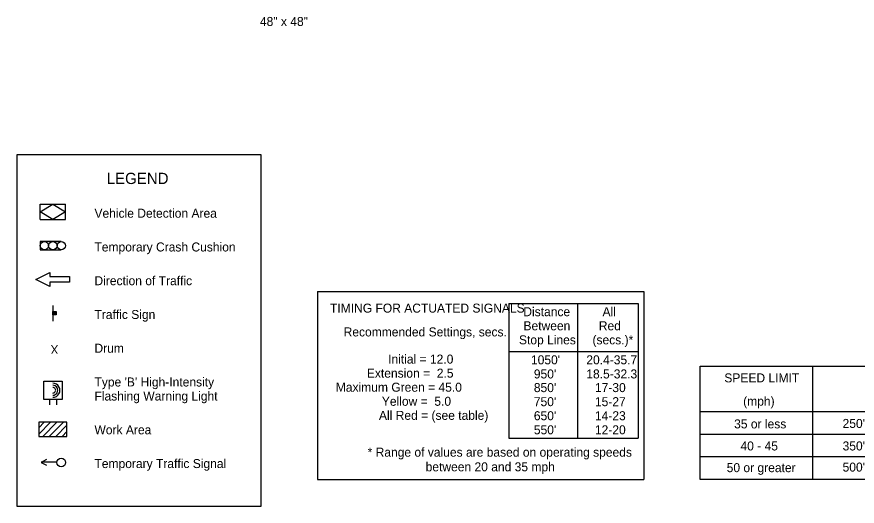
# Model space of a CAD drawing. Extents: x 10124 to 16850, y 7924 to 12166.
# Drawn here: x 13749 to 15243, y 7951 to 8821 of the extents above; entities that cross this region are included whole.
import ezdxf

# ---------------------------------------------------------------- set-up
doc = ezdxf.new("R2010")
doc.units = 0
for name, color, linetype in [('Level 2', 7, 'Continuous'), ('Level 3', 7, 'Continuous'), ('Level 4', 7, 'Continuous')]:
    doc.layers.add(name, color=color, linetype=linetype)

msp = doc.modelspace()

# ---------------------------------------------------------------- linework, layer by layer
at = {"layer": 'Level 2'}
for p, q in [((13790.9, 8460.9), (13790.9, 8487.9)), ((13790.9, 8487.9), (13835.9, 8487.9)), ((13835.9, 8460.9), (13835.9, 8487.9)), ((13790.9, 8460.9), (13835.9, 8460.9)), ((13790.9, 8421.9), (13790.9, 8406.9)), ((13828.4, 8421.9), (13790.9, 8421.9)), ((13790.9, 8406.9), (13828.4, 8406.9)), ((14283.7, 8333), (14283.7, 7999)), ((14283.7, 8333), (14863.7, 8333)), ((14863.7, 8333), (14863.7, 7999)), ((13813.4, 8308), (13813.4, 8280.5)), ((13813.8, 8291.6), (13813.8, 8297.2)), ((13814.1, 8297.2), (13814.1, 8291.6)), ((13814.4, 8291.6), (13814.4, 8297.2)), ((13814.6, 8297.2), (13814.6, 8291.6)), ((13814.9, 8291.6), (13814.9, 8297.2)), ((13815.1, 8297.2), (13815.1, 8291.6)), ((13815.4, 8291.6), (13815.4, 8297.2)), ((13815.7, 8297.2), (13815.7, 8291.6)), ((13815.9, 8291.6), (13815.9, 8297.2)), ((13816.2, 8297.2), (13816.2, 8291.6)), ((13816.6, 8291.6), (13816.6, 8297.2)), ((13817, 8297.2), (13817, 8291.6)), ((13817.2, 8291.6), (13817.2, 8297.2)), ((13817.7, 8297.2), (13817.7, 8291.6)), ((13817.9, 8291.6), (13817.9, 8297.2)), ((13818.2, 8297.2), (13818.2, 8291.6)), ((13818.4, 8291.6), (13818.4, 8297.2)), ((13818.7, 8297.2), (13818.7, 8291.6)), ((14963.7, 8200.3), (15303.7, 8200.3)), ((14963.7, 7999), (14963.7, 8200.3)), ((15163.7, 8200.3), (15163.7, 7999)), ((13807.2, 8141.2), (13807.2, 8131.2)), ((13819.7, 8141.2), (13819.7, 8131.2)), ((15303.7, 8119), (14963.7, 8119)), ((13788.4, 8079.4), (13809.4, 8100.4)), ((13788.4, 8090.7), (13798.1, 8100.4)), ((13795.7, 8075.4), (13820.7, 8100.4)), ((13807, 8075.4), (13832, 8100.4)), ((13818.4, 8075.4), (13838.4, 8095.5)), ((13829.7, 8075.4), (13838.4, 8084.1)), ((15303.7, 8079), (14963.7, 8079)), ((15303.7, 8039), (14963.7, 8039)), ((13820.6, 8029.4), (13792.6, 8029.4)), ((14283.7, 7999), (14863.7, 7999)), ((15303.7, 7999), (14963.7, 7999))]:
    msp.add_line(p, q, dxfattribs=at)
for points in [[(13749.3, 7951.3), (14183.7, 7951.3), (14183.7, 8575.7), (13749.3, 8575.7)], [(13843.1, 8359.4), (13843.1, 8349.4), (13808.1, 8349.4), (13808.1, 8341.9), (13783.1, 8354.4), (13808.1, 8366.9), (13808.1, 8359.4)], [(13813.5, 8291.6), (13813.5, 8297.2), (13819.1, 8297.2), (13819.1, 8291.6)], [(13797.2, 8141.2), (13797.2, 8173.7), (13829.7, 8173.7), (13829.7, 8141.2)], [(13788.4, 8075.4), (13838.4, 8075.4), (13838.4, 8100.4), (13788.4, 8100.4)]]:
    msp.add_lwpolyline(points, close=True, dxfattribs=at)
msp.add_lwpolyline([(13802.3, 8034.2), (13792.3, 8029.2), (13802.3, 8024.2)], dxfattribs=at)
for centre, radius in [((13798.4, 8414.4), 7.5), ((13798.4, 8414.4), 7.5), ((13813.4, 8414.4), 7.5), ((13813.4, 8414.4), 7.5), ((13828.4, 8414.4), 7.5), ((13828.4, 8414.4), 7.5), ((13828.3, 8029), 7.74)]:
    msp.add_circle(centre, radius, dxfattribs=at)
for radius in [12.5, 12.5, 8.75, 5]:
    msp.add_arc((13813.4, 8157.4), radius, 269.4041, 90.5445, dxfattribs=at)
at = {"layer": 'Level 3'}
for p, q in [((14623.7, 8311.5), (14623.7, 8072.4)), ((14623.7, 8311.5), (14853.7, 8311.5)), ((14746.1, 8311.5), (14746.1, 8072.4)), ((14853.7, 8311.5), (14853.7, 8072.4)), ((14623.7, 8226.5), (14853.7, 8226.5)), ((14623.7, 8072.4), (14853.7, 8072.4))]:
    msp.add_line(p, q, dxfattribs=at)
at = {"layer": 'Level 4'}
msp.add_lwpolyline([(13790.9, 8474.4), (13813.4, 8487.9), (13835.9, 8474.4), (13813.4, 8460.9)], close=True, dxfattribs=at)

# ---------------------------------------------------------------- texts
at = {"layer": 'Level 2'}
msp.add_text('48" x 48"', height=16, dxfattribs=at).set_placement((14181.4, 8805))
msp.add_text('X', height=15, rotation=180, dxfattribs=at).set_placement((13822.9, 8237.7))
at = {"layer": 'Level 3'}
for s, height, p in [('LEGEND', 20, (13909, 8524)), ('Vehicle Detection Area', 16, (13887.3, 8464.1)), ('Temporary Crash Cushion', 16, (13887.3, 8404.1)), ('Direction of Traffic', 16, (13887.3, 8344.1)), ('TIMING FOR ACTUATED SIGNALS', 16, (14306, 8295.4)), ('Distance', 16, (14649.6, 8289)), ('All', 16, (14790.4, 8289)), ('Traffic Sign', 16, (13887.3, 8284.1)), ('Between', 16, (14649.9, 8264)), ('Red', 16, (14783.8, 8264)), ('Recommended Settings, secs.', 16, (14330.2, 8253.1)), ('Stop Lines', 16, (14641.9, 8239)), (' (secs.)*', 16, (14766.6, 8239)), ('Drum', 16, (13887.3, 8224.1)), ('Initial = 12.0', 16, (14409.3, 8204.8)), ("1050'", 16, (14663.2, 8203.5)), ('20.4-35.7', 16, (14761.6, 8203.5)), ('Extension =  2.5', 16, (14371.5, 8179.8)), ("950'", 16, (14668.3, 8178.4)), ('18.5-32.3', 16, (14761.6, 8178.4)), ('SPEED LIMIT', 16, (15006.9, 8171.4)), ("Type 'B' High-Intensity", 16, (13887.3, 8164.1)), ('Maximum Green = 45.0', 16, (14316.3, 8154.8)), ("850'", 16, (14668.3, 8154.1)), ('17-30', 16, (14776.9, 8154.1)), ('Flashing Warning Light', 16, (13887.3, 8139.1)), ('Yellow =  5.0', 16, (14398.1, 8129.8)), ("750'", 16, (14668.3, 8129.1)), ('15-27', 16, (14776.9, 8129.1)), ('(mph)', 16, (15040.4, 8130)), ('All Red = (see table)', 16, (14393, 8104.8)), ("650'", 16, (14668.3, 8104.1)), ('14-23', 16, (14776.9, 8104.1)), ('35 or less', 16, (15024.3, 8089.6)), ("250'", 16, (15217.1, 8090.4)), ('Work Area', 16, (13887.3, 8079.1)), ("550'", 16, (14668.3, 8079.1)), ('12-20', 16, (14776.9, 8079.1)), ('40 - 45', 16, (15035.6, 8050.4)), ("350'", 16, (15217.1, 8050.4)), ('* Range of values are based on operating speeds', 16, (14372.8, 8039.3)), ('Temporary Traffic Signal', 16, (13887.3, 8019.1)), ('between 20 and 35 mph', 16, (14476, 8013.3)), ('50 or greater', 16, (15011.1, 8011.8)), ("500'", 16, (15217.1, 8012.8))]:
    msp.add_text(s, height=height, dxfattribs=at).set_placement(p)

doc.saveas('drawing.dxf')
